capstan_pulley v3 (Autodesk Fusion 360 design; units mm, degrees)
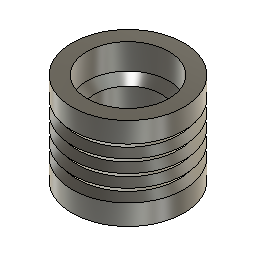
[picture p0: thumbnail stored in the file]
parameter "teeth" = 1
sketch "Sketch1" plane through (0, 0, 0) normal (0, 0, 1) x axis (1, 0, 0)
  circle C1 centre (0, 0) radius 10.936
  point P1 (0, 0)
  point P2 (0, 0)
  coincident P1 P2
  dimension "d1" diameter C1 = 21.872 (= "20.372 mm + 2 * teeth - 0.5 mm")
extrude "Extrude1" new body sketch "Sketch1" distance 18
sketch "Sketch2" plane through (0, 0, 9) normal (0, 0, 1) x axis (-1, 0, 0)
  circle C1 centre (0, 0) radius 10.936
  circle C2 centre (0, 0) radius 8.02
  concentric C1 C2
  dimension "d4" diameter C2 = 16.04
extrude "Extrude2" cut sketch "Sketch2" profile of C2 against normal blind 26
sketch "Sketch3" plane through (0, 0, 0) normal (0, 1, 0) x axis (1, 0, 0)
  line L1 (10.936, -9) -> (-10.936, -9)
  line L2 (10.936, 9) -> (-10.936, 9)
  line L3 (10.936, 9) -> (10.936, -9)
  line L4 (9.936, 1.25) -> (10.936, 0)
  line L5 (10.936, 2.5) -> (9.936, 1.25)
  line L6 (10.936, 0) -> (10.936, 2.5)
  point P3 (10.936, -9)
  point P6 (10.936, -9)
  point P5 (10.936, 9)
  point P7 (10.936, 9)
  point P8 (10.936, 0)
  point P10 (10.936, 2.5)
  point P11 (10.936, 1.25)
  point P9 (9.936, 1.25)
  point P1 (0, 0)
  coincident P3 P6
  coincident P5 P7
  coincident L3 P8
  coincident L3 P10
  midpoint L6 P11
  horizontal P9 P11
  horizontal P1 P8
  dimension "d7" distance P8 P10 = 2.5
  dimension "d8" distance P9 P10 = 1 (= "teeth")
revolve "Revolve1" sketch "Sketch3" AlongAngle 360
rectangular_pattern "R-Pattern1" uSpaceDistance 2.5 vSpaceDistance 0
work_plane "WorkPlane1" AlongDistance -11
sketch "Sketch5" plane through (0, 0, 0) normal (0, 1, 0) x axis (1, 0, 0)
  line L1 (6.52, 2.5) -> (6.52, -2.5)
  line L2 (8.02, -4) -> (6.52, -2.5)
  line L3 (8.02, 4) -> (6.52, 2.5)
  line L4 (8.02, 4) -> (8.02, -4)
  point P4 (8.02, -9)
  point P6 (8.02, -4)
  point P5 (8.02, 9)
  point P7 (8.02, 4)
  point P8 (6.52, 0)
  point P9 (0, 0)
  point P2 (6.52, -2.5)
  vertical L1
  vertical P4 P6
  vertical P5 P7
  midpoint L1 P8
  horizontal P8 P9
  dimension "d18" angle L1 L3 = 45
  dimension "d19" angle L1 L2 = 45
  dimension "d20" distance P4 P6 = 5
  dimension "d21" distance P2 P6 = 1.5
revolve "Revolve2" sketch "Sketch5" AlongAngle 360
